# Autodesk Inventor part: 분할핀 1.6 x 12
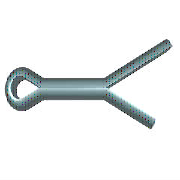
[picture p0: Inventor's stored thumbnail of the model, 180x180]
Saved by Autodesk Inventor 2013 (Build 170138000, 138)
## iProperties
IsCustomPart: 1
Created: 2012-02
Part Number: 분할핀 1.6 x 12
Material: 강철, 연강
Description: 분할 핀
Document SubType Name: Modeling
Standard: KS B 1321
Designer: mduedu
Standards Organization: KS
Language: ko-KR
Size Designation: 1.6 x  12
Categories: <MemberInstance><Categories><Category DisplayName="조임쇠" InternalName="e4da775c-781d-43d5-af7c-5136215cf5a6" Mnemonic="FSTN"><Category DisplayName="핀" InternalNa
Density: 1 g/cm^3
Author: mduedu
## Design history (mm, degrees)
sketch "스케치1"
  geometry: L1 (0, 0.7)-(7, 0.7); L2 (0, -0.7)-(7, -0.7); L3 (7, 0.7)-(12, 2.616); L4 (12, 2.616)-(12.234, 2.005); L5 (12.234, 2.005)-(7, 0); L6 (7, 0)-(14.734, -2.963); L7 (14.734, -2.963)-(14.5, -3.573); L8 (14.5, -3.573)-(7, -0.7); L9 (0, 0)-(-1.528, -0.645); L10 (0, 0)-(-1.528, 0.645); L11 (0, 0.7)-(0, -0.7); L12 (0, 0.7)-(-1.204, 1.267); L13 (0, -0.7)-(-1.204, -1.267); L14 (-3.2, 0)-(7, 0); L15 (7, 0.7)-(7, -0.7); A1 r 1.4 centre (-1.8, 0) between (-1.204, 1.267) and (-1.204, -1.267); A2 r 0.7 centre (-1.8, 0) between (-1.528, 0.645) and (-1.528, -0.645); 1 further point
  constraints: 30 end point, 5 point on circle, 4 parallel, 4 perpendicular, 4 point on line, 4 tangent, 2 centre point, 2 midpoint, 1 coincident, 1 horizontal
  dimensions: "d0" = 7 distance of L1.start L1.end (= MSIAB); "d1" = 12 horizontal distance of L1.start L3.end (= SNLG); "d2" = 159.037 deg angle of L1 L3; "d3" = 159.037 deg angle of L2 L8; "d4" = 2.5 horizontal distance of L3.end L7.end (= LGDIF); "d5" = 0.7 radius of A2 (= -0.5 x SNND1 + 0.5 x KBR); "d6" = 1.4 radius of A1 (= 0.5 x KBR); "d7" = 0.7 distance from line of L1 L9.start (= 0.5 x SNND1); "d8" = 0.7 distance between parallel lines of L2 L14 (= 0.5 x SNND1); "d9" = 1.8 distance from line of L11 A1.centre (= KOL - 0.5 x KBR)
extrude "본체" new body sketch "스케치1" stored distance "d10" = 1.4 (= SNND1); taper "d11" = 0 deg
workaxis "Work Axis1"
workplane "Work Plane1"
workplane "Work Plane3"
node "작업 평면3"
body "Solid1"
fillet "모깎기" dims "d12" = 0.49 (= 0.35 x SNND1)
other parameters: "SNND" = 1.6 [user parameter], "SNLG" = 12 [user parameter; used in 1 equation term], "SNND1" = 1.4 [user parameter; used in 5 equation terms], "KBR" = 2.8 [user parameter; used in 3 equation terms], "KOL" = 3.2 [user parameter; used in 1 equation term], "LGDIF" = 2.5 [user parameter; used in 1 equation term], "MSIAB" = 7 [user parameter; used in 1 equation term], "d15" = 0, "d16" = 0, "d17" = 0, "NNDMAX" = 7 [user parameter], "DSH" = 6 [user parameter], "NNDMIN" = 5.5 [user parameter], "d18" = -3.25
